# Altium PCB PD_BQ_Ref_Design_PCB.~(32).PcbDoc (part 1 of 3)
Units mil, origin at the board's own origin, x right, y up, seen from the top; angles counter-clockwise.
Board outline 2000 x 3702.76 mil, 4 copper layers (Top Layer, Signal Layer 1, Signal Layer 2, Bottom Layer), stack 61.2 mil thick; 124 components, 53 nets, 359 pads, 494 vias.
Unrouted connection lines stored in the file: 227.
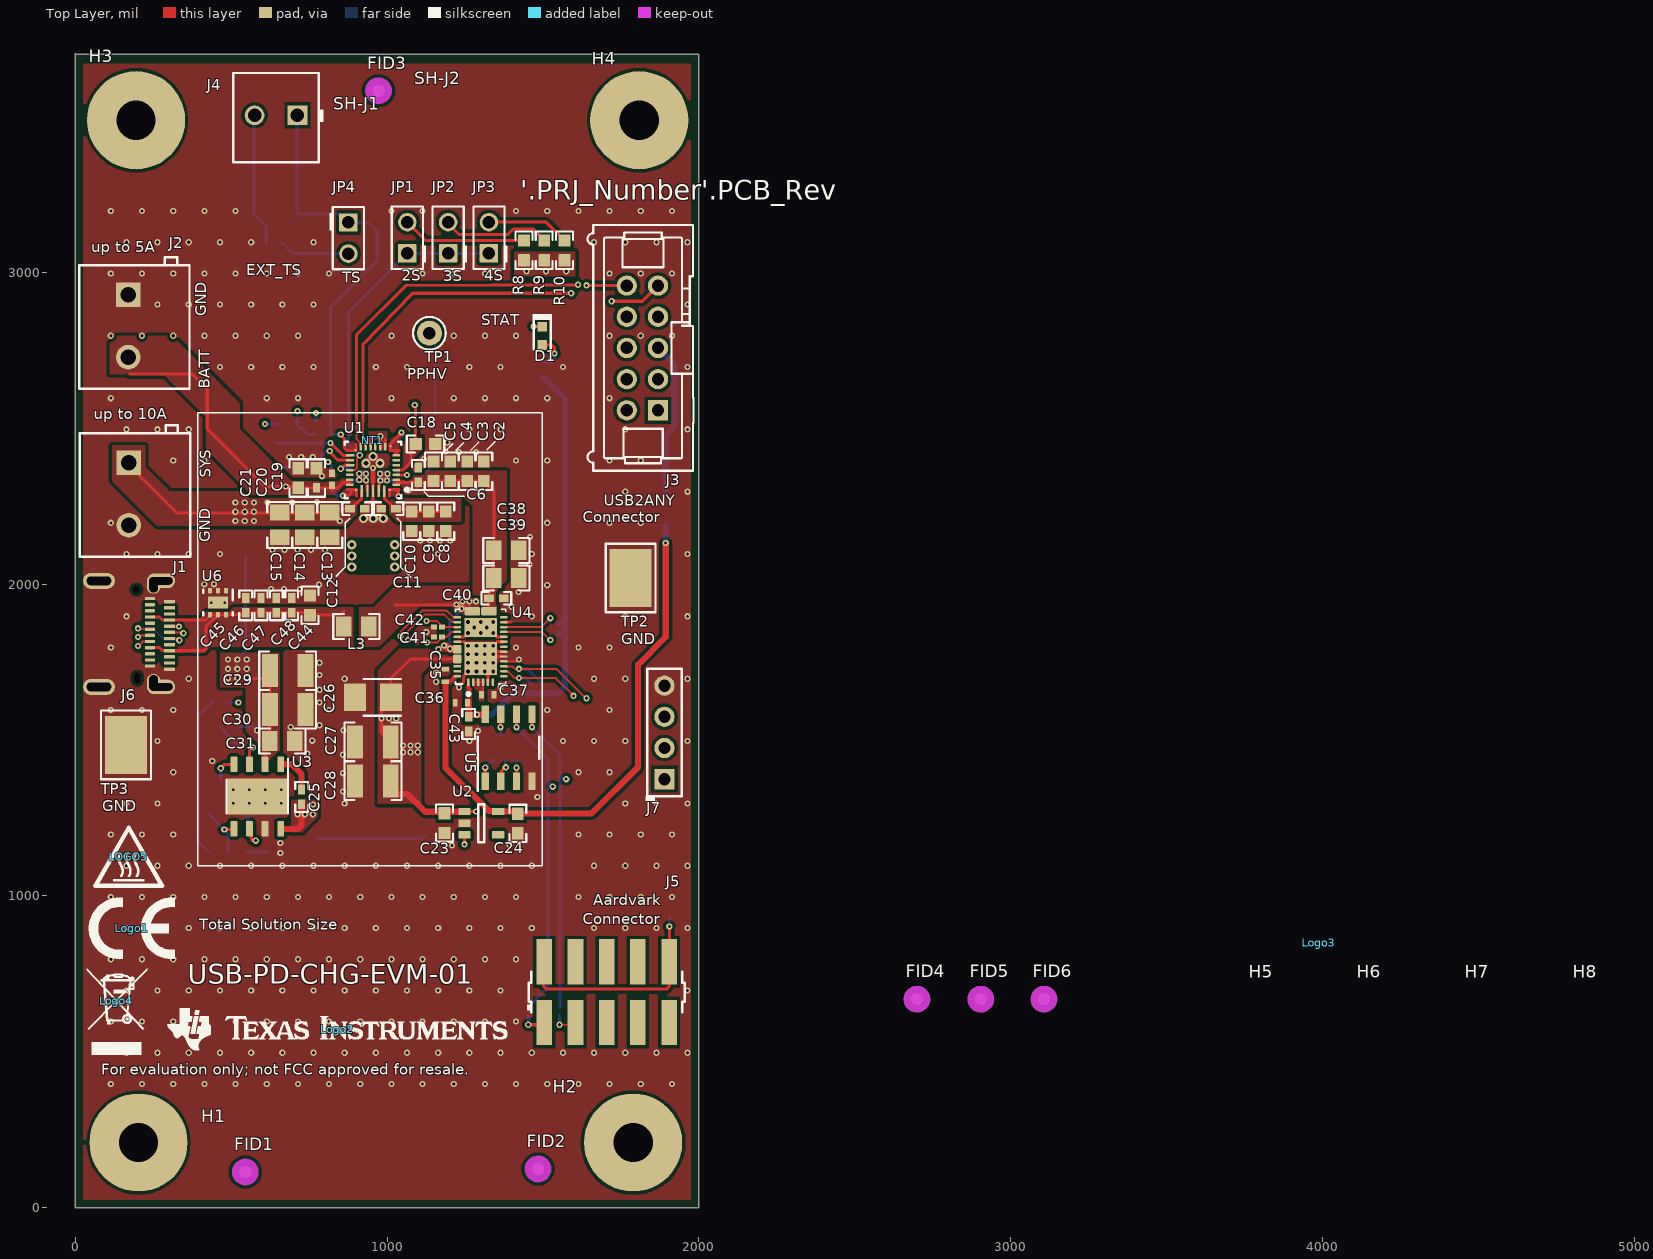
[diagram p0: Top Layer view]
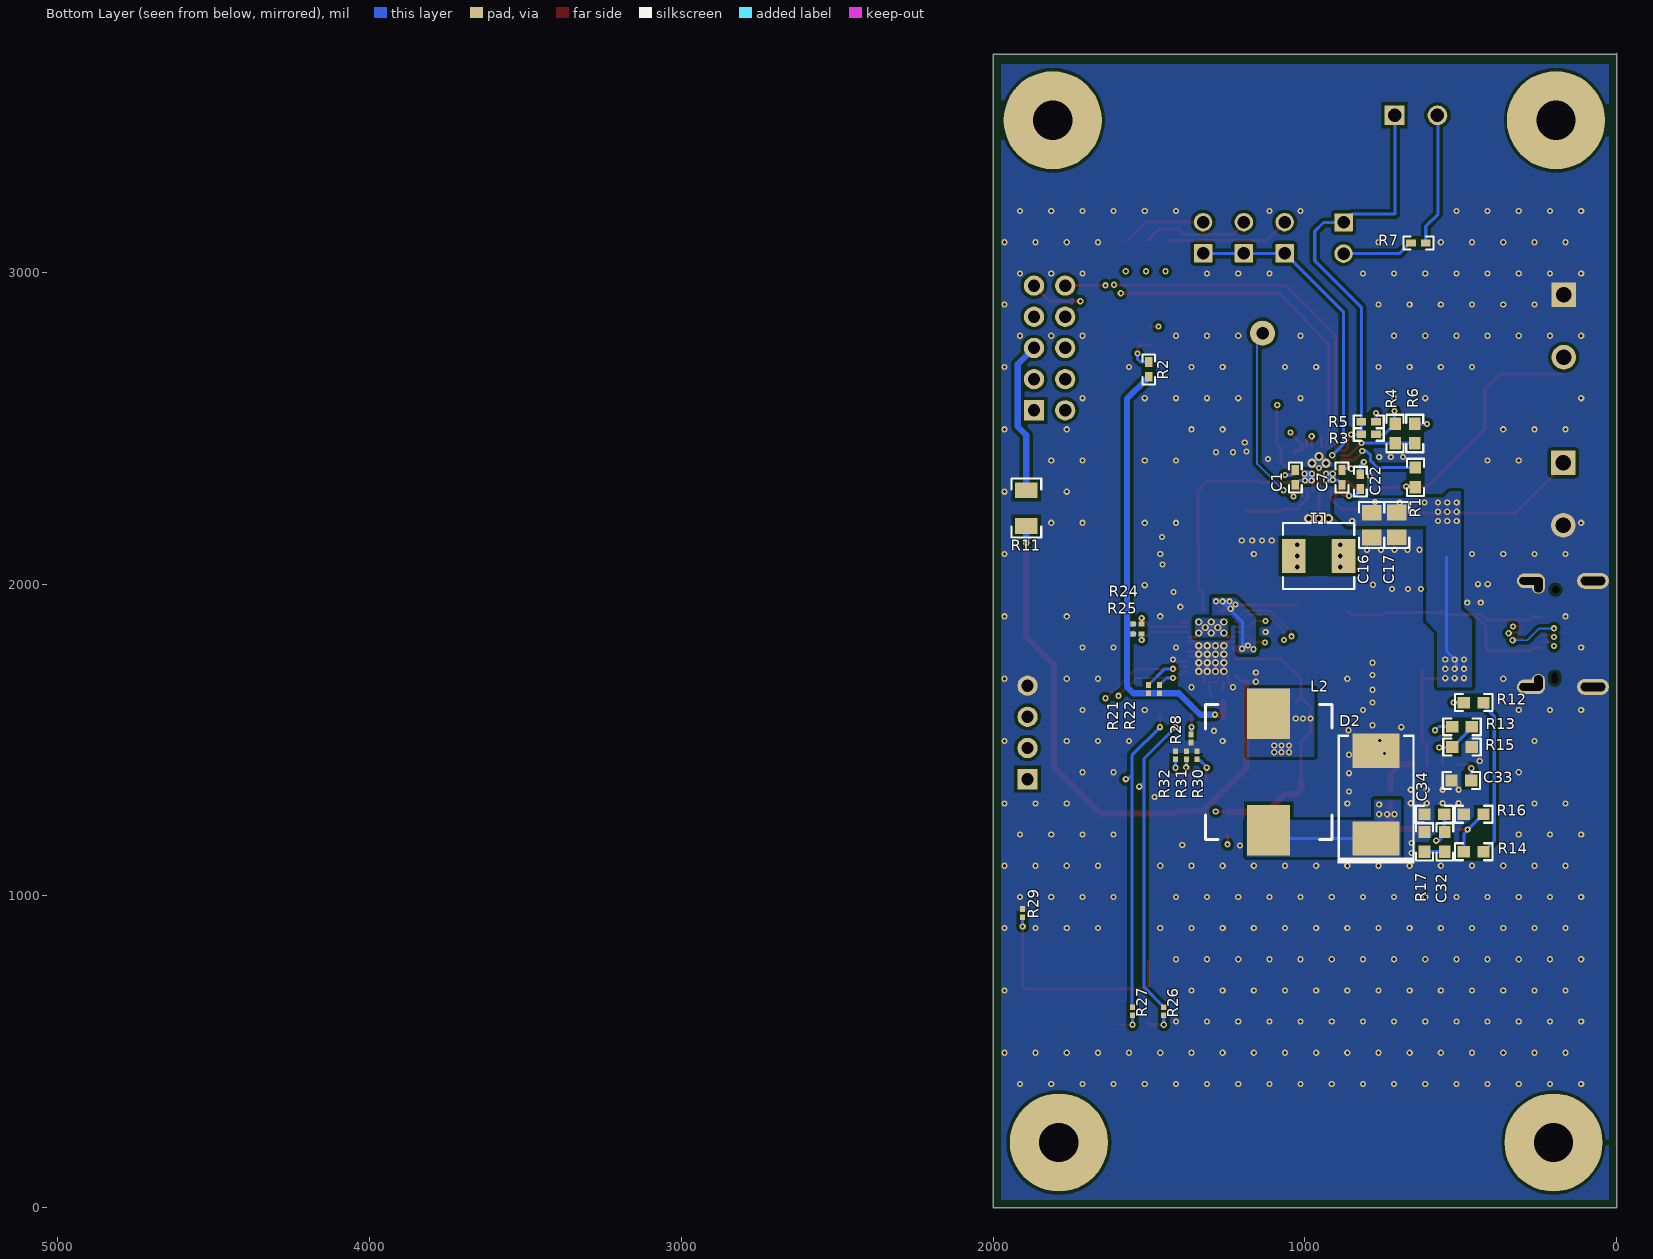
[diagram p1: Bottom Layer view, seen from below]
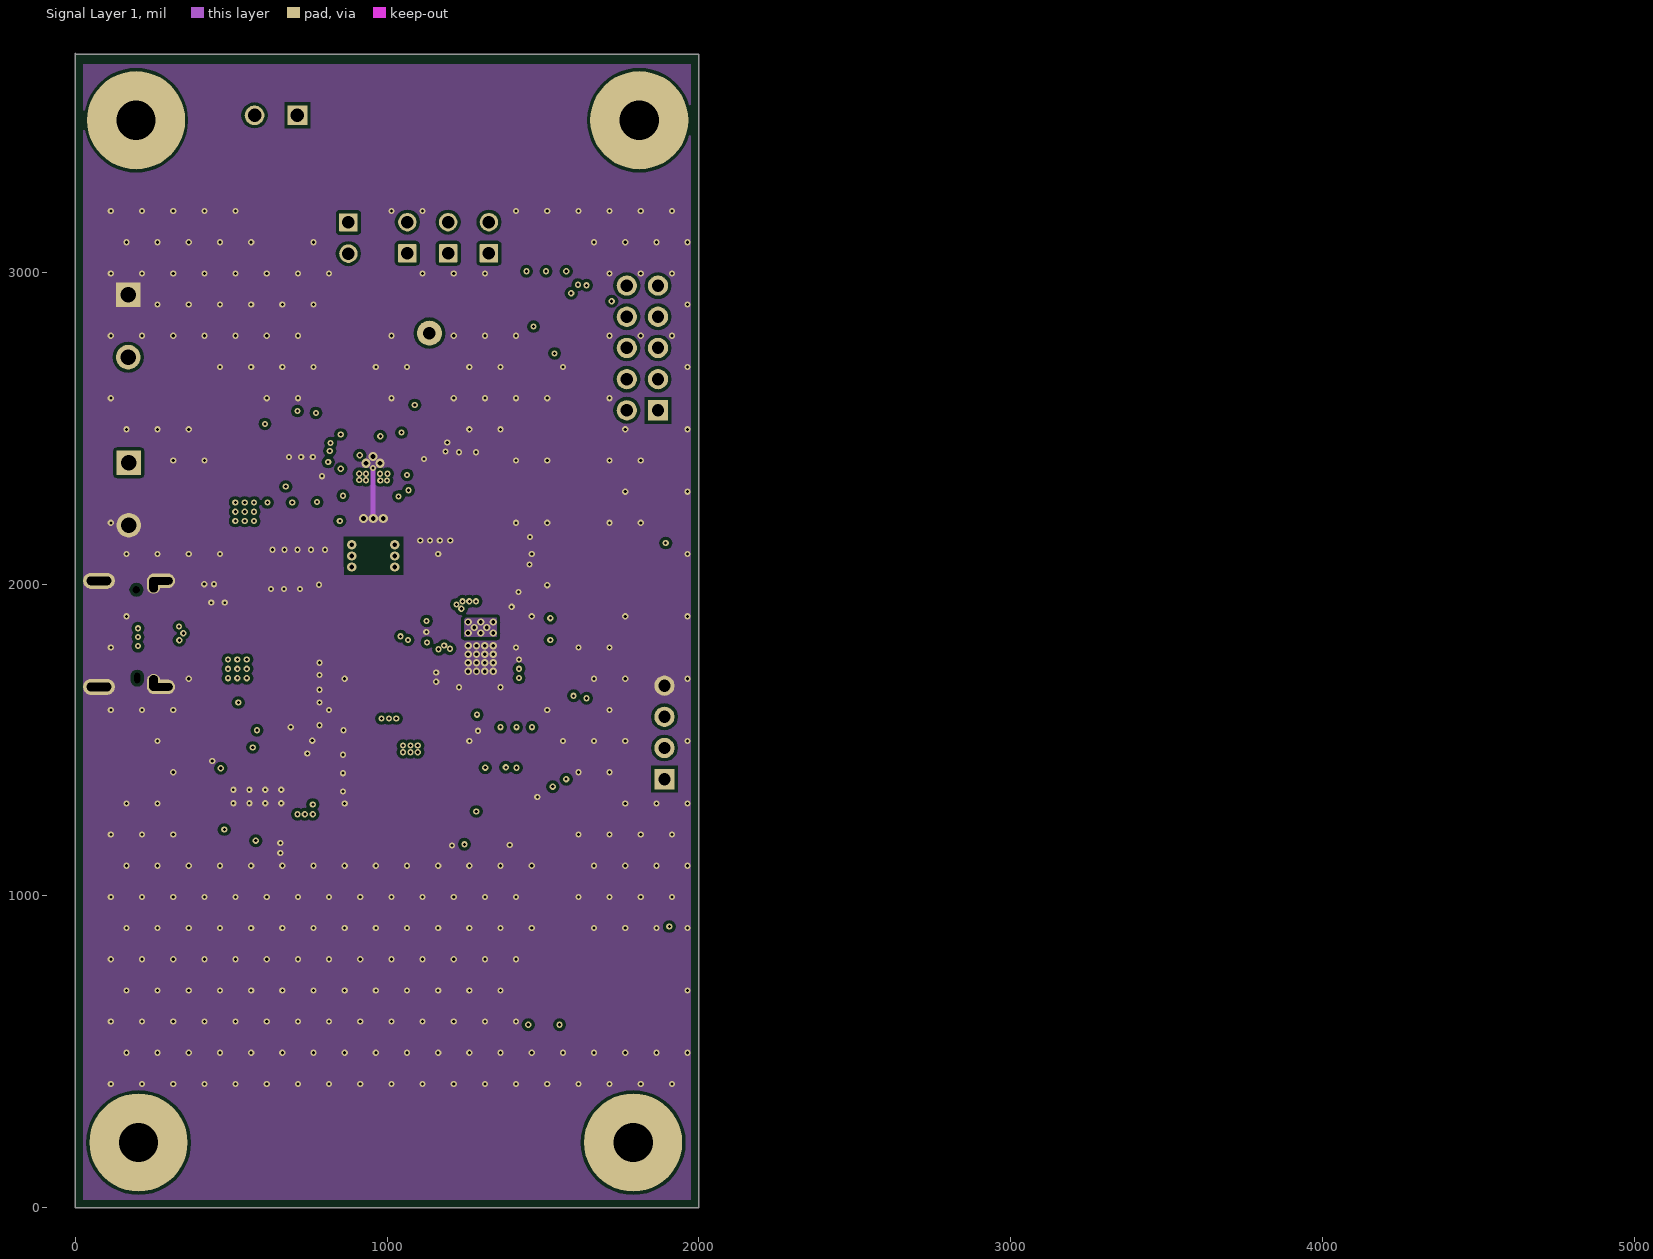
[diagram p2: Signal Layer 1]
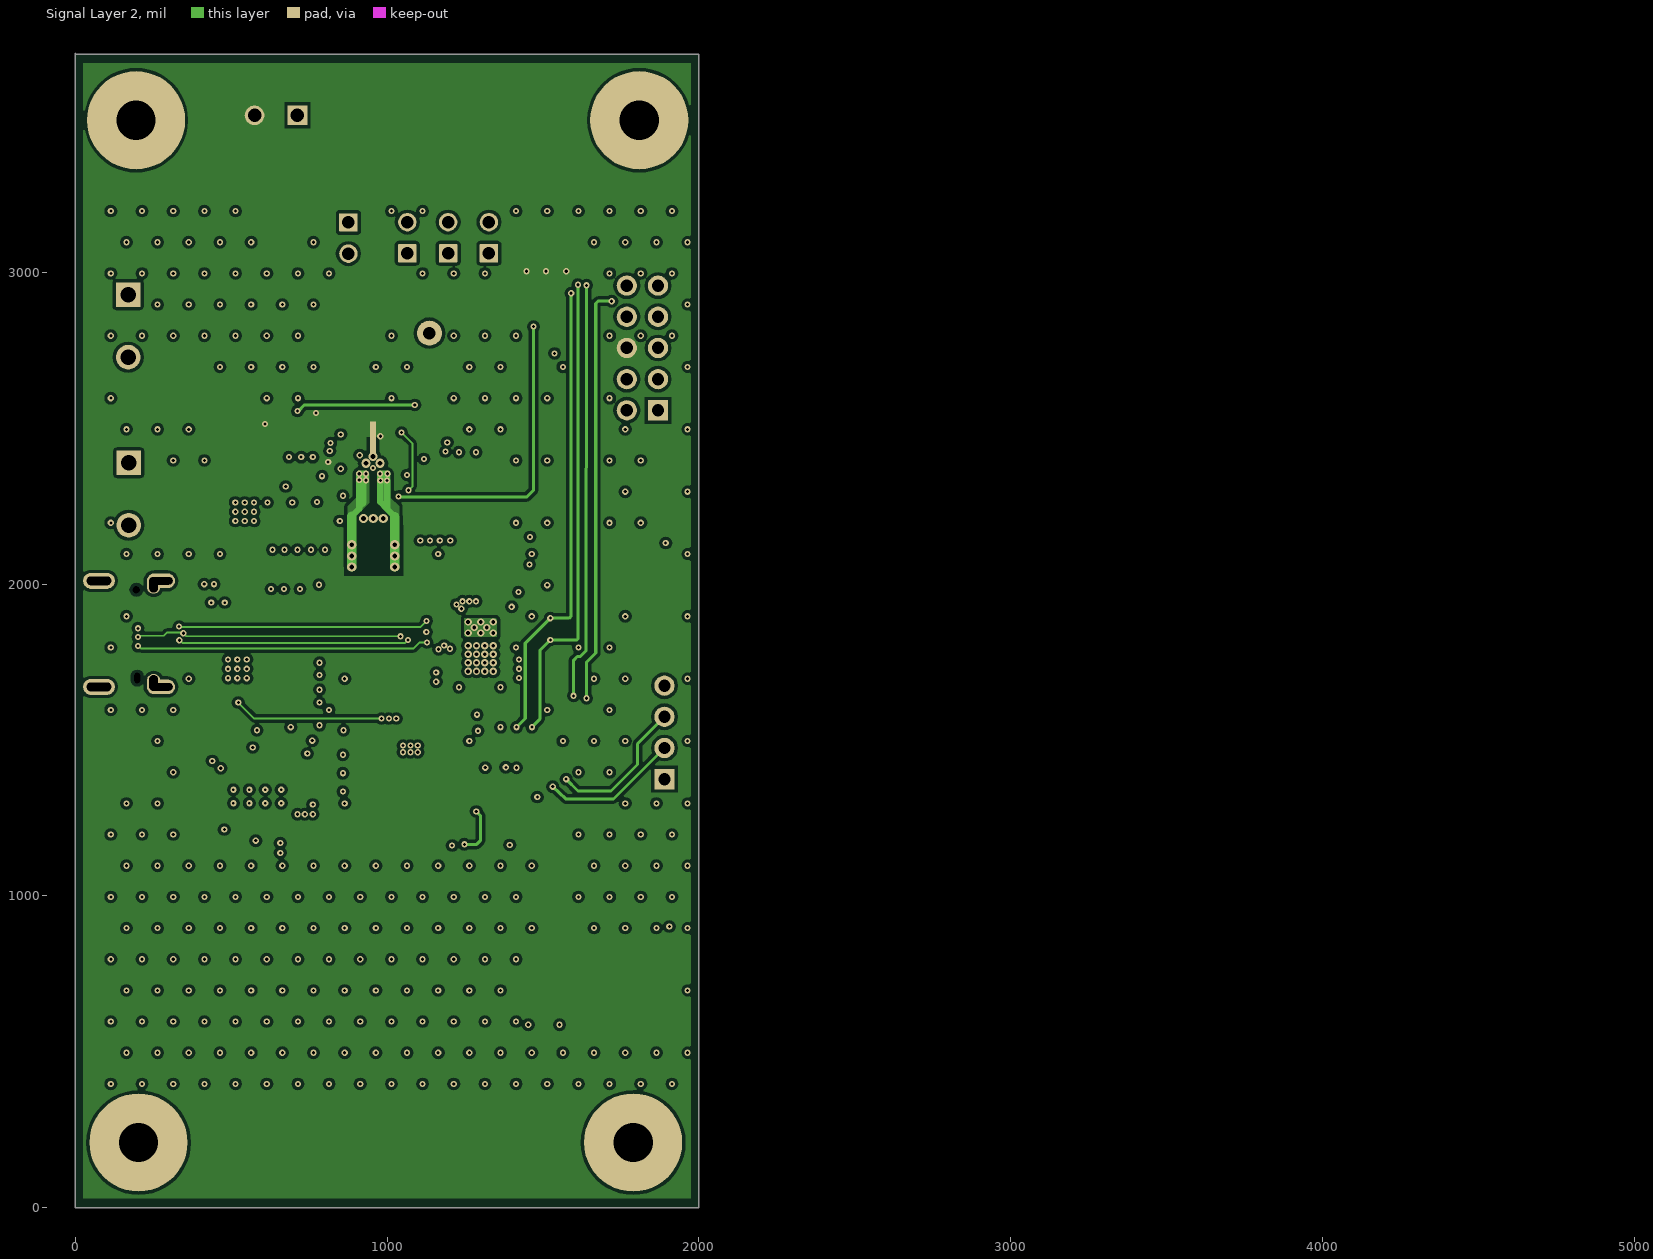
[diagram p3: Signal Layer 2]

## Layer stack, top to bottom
Top Solder: solder mask 0.4, Solder Resist, Dk 3.5
Top Layer: signal copper 2.8
Dielectric 1: prepreg 12, FR-4 High TG, Dk 4.2
Signal Layer 1: signal copper 2.8
Dielectric2: core 26, FR-4 High TG, Dk 4.2
Signal Layer 2: signal copper 2.8
Dielectric3: prepreg 12, FR-4 High TG, Dk 4.2
Bottom Layer: signal copper 2.8
Bottom Solder: solder mask 0.4, Solder Resist, Dk 3.5

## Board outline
0,0 2000,0 2000,3700 2.76,3700 0,3702.76

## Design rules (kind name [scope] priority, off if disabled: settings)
AcuteAngle [All] p1: minimum=4.50000000000000E+0001 checktracksonly=FALSE
AssemblyTestPointUsage [All] p1: valid=2
BoardOutlineClearance BoardOutlineClearance_MountingHoles [OnCopper and InComponentClass('Mounting Holes')] p1: gap=39.37 ignorepadtopadclearanceinfootprint=FALSE
BoardOutlineClearance BoardOutlineClearance_Poly [OnCopper and IsPoly] p2: gap=25 ignorepadtopadclearanceinfootprint=FALSE
BoardOutlineClearance [OnCopper and Not InComponentClass('Logo') and not InComponentClass('FiducialMark') and not InRegion(1000,500,4000,800) and not InPoly] p3: gap=15 ignorepadtopadclearanceinfootprint=FALSE
Clearance Clearance_Keepouts [((IsTrack Or IsArc) And Not InPoly) And IsFree and IsKeepOut vs ((IsTrack Or IsArc) And Not InPoly) And IsFree and IsKeepOut] p1: gap=0 ignorepadtopadclearanceinfootprint=FALSE
Clearance Clearance_Poly [InPolygon] p2: gap=10 ignorepadtopadclearanceinfootprint=TRUE
Clearance Clearance_FiducialMark [IsKeepOut and InComponentClass('FiducialMark') vs IsPad and InComponentClass('FiducialMark')] p3: gap=0 ignorepadtopadclearanceinfootprint=FALSE
Clearance [All] p4: gap=5 ignorepadtopadclearanceinfootprint=TRUE
ComponentClearance ComponentClearance_MountingHoles_FiducialMarks [InComponentClass('Mounting Holes') vs InComponentClass('FiducialMark')] p1: gap=50 collisioncheckmode=3 verticalgap=10 showdistances=FALSE
ComponentClearance ComponentClearance_Shunt [InComponentClass('Header') vs InComponentClass('Shunt')] p2: gap=0 collisioncheckmode=3 verticalgap=0 showdistances=FALSE
ComponentClearance ComponentClearance_Logo [InComponentClass('Logo')] p3: gap=50 collisioncheckmode=3 verticalgap=10 showdistances=FALSE
ComponentClearance ComponentClearance_ScrewToNut [(HasFootprint('NY PMS 440 0025 PH')) vs (HasFootprint('Keystone_1902C'))] p4: gap=5 collisioncheckmode=3 verticalgap=10 showdistances=FALSE
ComponentClearance ComponentClearance_MountingHoles [InComponentClass('Mounting Holes')] p5: gap=100 collisioncheckmode=3 verticalgap=100000 showdistances=FALSE
ComponentClearance ComponentClearance_SmallPassives [HasFootprint('0201*') or HasFootprint('0402*') or HasFootprint('0508') or HasFootprint('0603*') or HasFootprint('0612') or HasFootprint('0805*') or HasFootprint('0815*') or HasFootprint('0830*') or HasFootprint('1206*') or HasFootprint('1210*') or HasFootprint('1808*') or HasFootprint('1812*') or HasFootprint('1825*') or HasFootprint('2010*') or HasFootprint('2220*') or HasFootprint('2225*') or HasFootprint('2512*') or HasFootprint('2728*') or HasFootprint('3518*') vs HasFootprint('0201*') or HasFootprint('0402*') or HasFootprint('0508') or HasFootprint('0603*') or HasFootprint('0612') or HasFootprint('0805*') or HasFootprint('0815*') or HasFootprint('0830*') or HasFootprint('1206*') or HasFootprint('1210*') or HasFootprint('1808*') or HasFootprint('1812*') or HasFootprint('1825*') or HasFootprint('2010*') or HasFootprint('2220*') or HasFootprint('2225*') or HasFootprint('2512*') or HasFootprint('2728*') or HasFootprint('3518*')] p6: gap=14.96 collisioncheckmode=3 verticalgap=10 showdistances=FALSE
ComponentClearance ComponentClearance_THtoSMT [IsThruComponent vs IsSMTComponent] p7: gap=40 collisioncheckmode=3 verticalgap=30 showdistances=FALSE
ComponentClearance ComponentClearance_THtoTH [IsThruComponent vs IsThruComponent] p8: gap=30 collisioncheckmode=3 verticalgap=30 showdistances=FALSE
ComponentClearance [All] p9: gap=20 collisioncheckmode=3 verticalgap=10 showdistances=FALSE
DiffPairsRouting [All] p1: maxlimit=100 minlimit=10 mostfreqgap=10 toplayer_minwidth=15 toplayer_maxwidth=15 toplayer_prefwidth=15 midlayer1_minwidth=15 midlayer1_maxwidth=15 midlayer1_prefwidth=15 midlayer2_minwidth=15 midlayer2_maxwidth=15 midlayer2_prefwidth=15 bottomlayer_minwidth=15 bottomlayer_maxwidth=15 bottomlayer_prefwidth=15 maxuncoupledlength=1000
FabricationTestPointUsage TestPointUsage [All] p1: valid=2 allowmultiple=FALSE
FabricationTestpoint Testpoint [All] p1: side=3 testpointundercomponent=TRUE minsize=40 maxsize=100 preferedsize=60 minholesize=0 maxholesize=40 preferedholesize=32 testpointgrid=1 allowsidetop=TRUE allowsidebottom=TRUE usegrid=TRUE gridtolerance=0.01
FanoutControl Fanout_LCC [IsLCC] p1: bgadir=Out bgaviamode=Centered fanoutstyle=Auto fanoutdirection=Alternating viagrid=1 // Fanout_LCC (Default Rule)
FanoutControl Fanout_BGA [IsBGA] p2: bgadir=Out bgaviamode=Centered fanoutstyle=Auto fanoutdirection=Alternating viagrid=1 // Fanout_BGA (Default Rule)
FanoutControl Fanout_Default [All] p4: bgadir=Out bgaviamode=Centered fanoutstyle=Auto fanoutdirection=Alternating viagrid=1 // Fanout_Default (Default Rule)
FanoutControl Fanout_Small [(CompPinCount < 5)] p5: bgadir=Out bgaviamode=Centered fanoutstyle=Auto fanoutdirection=OutThenIn viagrid=1 // Fanout_Small (Default Rule)
HoleSize [All] p1: absolutevalues=TRUE maxlimit=251 minlimit=7.87 maxpercent=80.000 minpercent=20.000
MinimumAnnularRing MinimumAnnularRing_ThermalPadVias [IsVia and InAnyComponent] p1: minimumring=5.91
MinimumAnnularRing [All] p2: minimumring=5
MinimumSolderMaskSliver MinimumSolderMaskSliver_Logo [InComponentClass('Logo') vs InComponentClass('Logo')] p1: minsoldermaskwidth=0.7
MinimumSolderMaskSliver [All] p2: minsoldermaskwidth=3
PlaneConnect [All] p1: planeconnectstyle=Relief reliefexpansion=10 reliefentries=4 reliefconductorwidth=10 reliefairgap=10
PolygonConnect [All] p1: connectstyle=Direct reliefconductorwidth=10 reliefentries=4 polygonreliefangle="90 Angle" airgapwidth=10
RoutingVias ThermalPadVias [IsVia and InAnyComponent] p1: holewidth=7.87 width=19.68 viastyle="Through Hole" minholewidth=7.87 minwidth=19.68 maxholewidth=12.99 maxwidth=23.62
RoutingVias [All] p2: holewidth=10 width=20 viastyle="Through Hole" minholewidth=5 minwidth=10 maxholewidth=40 maxwidth=65
SilkToBoardRegionClearance [Not ((IsComment or IsDesignator) And (Hide <> 'False')) and not InRegion(1000,500,4000,800)] p1:
SilkToSilkClearance SilkToSilkClearance_Pb-FreeLogo [(HasFootprint('Pb-Free_Overlay_Medium') OR HasFootprint('Pb-Free_Overlay_Small')) vs (HasFootprint('Pb-Free_Overlay_Medium') OR HasFootprint('Pb-Free_Overlay_Small'))] p1: silktosilkclearance=0
SilkToSilkClearance [All] p2: silktosilkclearance=1
SilkToSolderMaskClearance SilkToComponentPadClearance [(IsPad or IsFill or IsRegion) and InAnycomponent] p1: minsilkscreentomaskgap=3 clearancetoexposedcopper=TRUE
SilkToSolderMaskClearance "Silk to Solder Mask Opening" [All] p2: minsilkscreentomaskgap=3.94 clearancetoexposedcopper=FALSE
SolderMaskExpansion [All] p1: expansion=1.97
UnRoutedNet [All] p1: checkbadconnections=TRUE
Width [All] p1: maxlimit=100 minlimit=6 preferedwidth=10 checkconnectedcopper=TRUE
14 further rules are at their usual default settings.

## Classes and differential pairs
component class Shunt: SH-J1 SH-J2
component class "Mounting Holes": H1 H2 H3 H4
component class FiducialMark: FID1 FID2 FID3 FID4 FID5 FID6
component class Logo: Logo2
component class Type_C_Port: C44 C45 C46 C47 C48 J6 L3 U6
component class TPS25750D: C35 C36 C37 C38 C39 C40 C41 C42 C43 J5 J7 R24 R25 R26 R27 R28 R29 R30 R31 R32 U4 U5
component class Power_5V_3.3V: C23 C24 C25 C26 C27 C28 C29 C30 C31 C32 C33 C34 D2 L2 R12 R13 R14 R15 R16 R17 U2 U3
component class Header: J5 J7 JP1 JP2 JP3 JP4
component class BQ25792: C1 C2 C3 C4 C5 C6 C7 C8 C9 C10 C11 C12 C13 C14 C15 C16 C17 C18 C19 C20 C21 C22 D1 J1 J2 J3 J4 JP1 JP2 JP3 JP4 L1 NT1 R1 R2 R3 R4 R5 R6 R7 R8 R9 R10 R11 R21 R22 TP1 TP2 TP3 U1
component class PD_BQ_Ref_Design_Hardware: FID1 FID2 FID3 FID4 FID5 FID6 H1 H2 H3 H4 H5 H6 H7 H8 Logo1 Logo2 Logo3 Logo4 LOGO5 SH-J1 SH-J2 ZZ1
component class AssemblyNote: ZZ1

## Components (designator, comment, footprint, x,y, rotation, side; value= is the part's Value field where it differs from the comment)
C1 "GRM155R71E473KA88D" 0402 1030.63,2342.52 r270 bottom value=0.047uF
C2 "GRT188R61E106ME13D" 0603#1 1310.16,2362.2 r270 top value=10uF
C3 "GRT188R61E106ME13D" 0603#1 1257.01,2362.2 r270 top value=10uF
C4 "GRT188R61E106ME13D" 0603#1 1202.87,2362.2 r270 top value=10uF
C5 "GRT188R61E106ME13D" 0603#1 1148.74,2362.2 r270 top value=10uF
C6 "C1005X7R1H104K050BE" 0402 1100.51,2350.39 r90 top value=0.1uF
C7 "GRM155R71E473KA88D" 0402 881.02,2342.52 r270 bottom value=0.047uF
C8 "GRT188R61E106ME13D" 0603#1 1188.11,2201.77 r90 top value=10uF
C9 "GRT188R61E106ME13D" 0603#1 1133.98,2201.77 r90 top value=10uF
C10 "GRT188R61E106ME13D" 0603#1 1078.86,2201.77 r90 top value=10uF
C11 "C1005X7R1H104K050BE" 0402 1005.04,2242.13 r180 top value=0.1uF
C12 "C1005X7R1H104K050BE" 0402 904.65,2242.13 r0 top value=0.1uF
C13 "C2012X5R1E106K125AB" 0805_HV 816.06,2189.96 r270 top value=10uF
C14 "C2012X5R1E106K125AB" 0805_HV 735.35,2189.96 r270 top value=10uF
C15 "C2012X5R1E106K125AB" 0805_HV 655.63,2189.96 r270 top value=10uF
C16 "C2012X5R1E106K125AB" 0805_HV 786.06,2189.61 r270 bottom value=10uF
C17 "C2012X5R1E106K125AB" 0805_HV 705.35,2189.96 r270 bottom value=10uF
C18 "GRM188R61C475KAAJ" 0603#1 1123.15,2449.8 r0 top value=4.7uF
C19 "C1005X7R1H104K050BE" 0402L 822.83,2336.61 r90 top value=0.1uF
C20 "GRT188R61E106ME13D" 0603#2 773.74,2340.55 r90 top value=10uF
C21 "GRT188R61E106ME13D" 0603#1 714.68,2340.55 r90 top value=10uF
C22 "C0402C102K5RACTU" 0402 821.97,2328.74 r90 bottom value=1000pF
C23 "GRT188R61E106ME13D" 0603#1 1184.05,1233.36 r90 top value=10uF
C24 "GRT188R61E106ME13D" 0603#1 1419.46,1232.38 r90 top value=10uF
C25 "C1005X7R1H104K050BE" 0402 725.65,1317.47 r270 top value=0.1uF
C26 "T520B107M006ATE015" 3528-21 954.72,1636.81 r180 top value=100uF
C27 "GRM32ER61A476KE20L" 1210_270 954.72,1494.09 r180 top value=47uF
C28 "GRM32ER61A476KE20L" 1210_270 954.72,1369.09 r180 top value=47uF
C29 "GRM32ER71H475KA88L" 1210_270 681.1,1722.44 r0 top value=4.7uF
C30 "GRM32ER71H475KA88L" 1210_270 681.1,1598.43 r0 top value=4.7uF
C31 "GRM216R71H103KA01D" 0805_HV 664.18,1496.75 r0 top value=0.01uF
C32 "GRM188R71H222KA01D" 0603#1 551.18,1173.23 r270 bottom value=2200pF
C33 "06031C103KAT2A" 0603#1 498.03,1370.08 r0 bottom value=0.01uF
C34 "GRM1885C1H220JA01D" 0603#1 584.65,1261.81 r0 bottom value=22pF
C35 "CL05A106MP5NUNC" 0402_070 1187.01,1706.69 r90 top value=10uF
C36 "CL05A106MP5NUNC" 0402_070 1238.19,1620.08 r180 top value=10uF
C37 "CL05A106MP5NUNC" 0402_070 1322.83,1645.67 r0 top value=10uF
C38 "C2012X5R1V226M125AC" 0805_HV 1382.69,2108.19 r0 top value=22uF
C39 "C2012X5R1V226M125AC" 0805_HV 1382.69,2019.61 r0 top value=22uF
C40 "GMK105BJ104KV-F" 0402 1350.39,1954.72 r0 top value=0.1uF
C41 "GRM033R71H331KA12D" 0201_033 1163.39,1830.71 r180 top value=330pF
C42 "GRM033R71H331KA12D" 0201_033 1163.39,1862.2 r180 top value=330pF
C43 "GMK105BJ104KV-F" 0402 1261.81,1551.18 r270 top value=0.1uF
C44 "GRM188R6YA475KE15D" 0603#1 752.95,1932.09 r90 top value=4.7uF
C45 "C0402C103J5RACTU" 0402 546.26,1932.09 r270 top value=0.01uF
C46 "C0402C103J5RACTU" 0402 595.47,1932.09 r270 top value=0.01uF
C47 "C0402C103J5RACTU" 0402 644.68,1932.09 r270 top value=0.01uF
C48 "C0402C103J5RACTU" 0402 693.9,1932.09 r270 top value=0.01uF
D1 "LTST-C190GKT" LED_LTST-C190 1498.03,2796.26 r90 top value=Green
D2 "CDBC540-G" SMC 771.65,1324.8 r90 bottom value=40V
FID1 "Fiducial" Fiducial10-20 545.28,114.17 r0 top
FID2 "Fiducial" Fiducial10-20 1484.25,124.02 r0 top
FID3 "Fiducial" Fiducial10-20 972.56,3582.68 r0 top
FID4 "Fiducial" Fiducial10-20 2699.73,668.75 r0 top
FID5 "Fiducial" Fiducial10-20 2904.45,668.75 r0 top
FID6 "Fiducial" Fiducial10-20 3107.2,668.75 r0 top
H1 "NY PMS 440 0025 PH" "NY PMS 440 0025 PH"#1 202.76,208.66 r0 top
H2 "NY PMS 440 0025 PH" "NY PMS 440 0025 PH"#2 1789.37,279.53 r0 top
H3 "NY PMS 440 0025 PH" "NY PMS 440 0025 PH"#1 194.88,3488.19 r0 top
H4 "NY PMS 440 0025 PH" "NY PMS 440 0025 PH"#1 1809.06,3488.19 r0 top
H5 "1902C" Keystone_1902C 3904.45,582.14 r0 top
H6 "1902C" Keystone_1902C 4250.9,582.14 r0 top
H7 "1902C" Keystone_1902C 4597.36,582.14 r0 top
H8 "1902C" Keystone_1902C 4943.82,582.14 r0 top
J1 "ED120/2DS" On-Shore_ED120_2DS 171.26,2289.37 r270 top
J2 "ED120/2DS" On-Shore_ED120_2DS 169.29,2828.35 r270 top
J3 "N2510-6002-RB" CONN_2510-6002 1819.09,2757.68 r90 top
J4 "0393570002" MOLEX_39357-0002 643.7,3503.94 r180 top
J5 "TSM-105-01-L-DV-P" Samtec_TSM-105-01-x-DV 1704.54,691.02 r90 top
J6 "DX07S024JJ2R1300" JAE_DX07S024JJ2R1300 4.92,1840.55 r270 top
J7 "PEC04SAAN" SULLINS_PEC04SAAN 1889.76,1524.41 r90 top
JP1 "Header_2x1" CONN_PEC02SAAN 1064.96,3111.22 r90 top
JP2 "Header_2x1" CONN_PEC02SAAN 1195.87,3111.22 r90 top
JP3 "Header_2x1" CONN_PEC02SAAN 1326.77,3111.22 r90 top
JP4 "Header_2x1" CONN_PEC02SAAN 875.98,3110.24 r270 top
L1 "IHLP2020BZER1R0M11" IHLP-2020BZ 955.83,2090.43 r180 bottom value=1uH
L2 "74437368047" WE-LHMI_1040 1116.14,1397.64 r90 bottom value=4.7uH
L3 "FBMJ2125HM210NT" 0805_HV 901.57,1864.17 r0 top value="21 ohm"
Logo1 "CE Mark" CE_Mark_5mm 181.1,895.67 r0 top
Logo2 "Texas Instruments" TI_Horizontal_Overlay_Small 840.55,572.83 r0 top
Logo3 "FCC disclaimer" FCC_disclaimer 3989.17,850.39 r0 top
Logo4 "WEEE logo" WEEE_Minimum 131.89,663.39 r0 top
LOGO5 "CAUTION HOT SURFACE" IEC_HotSurface_Small 171.26,1125.98 r0 top
NT1 "Net-Tie" Net-Tie_20milWide_60milLong 954.72,2461.1 r90 top net-tie
R1 "RC0603FR-07100RL" 0603#1 645.67,2342.52 r90 bottom value=100
R2 "CRCW04022K21FKED" 0402 1500.98,2688.98 r270 bottom value=2.21k
R3 "Resistor" 0402 795.39,2480.31 r180 bottom value=5.23k
R4 "RC0603FR-07137KL" 0603#1 710.68,2483.27 r90 bottom value=137k
R5 "Resistor" 0402 795.39,2520.67 r0 bottom value=30.1k
R6 "RC0603FR-07100KL" 0603#1 647.82,2483.27 r270 bottom value=100k
R7 "Resistor" 0402 635.83,3094.49 r0 bottom value=10.0k
R8 "RC0603FR-076K04L" 0603#1 1438.98,3070.87 r90 top value=6.04k
R9 "CRCW060310K5FKEA" 0603#1 1503.94,3070.87 r90 top value=10.5k
R10 "CRCW060317K4FKEA" 0603#1 1568.9,3070.87 r90 top value=17.4k
R11 "ERJ-8ENF10R0V" 1206 1893.7,2244.09 r270 bottom value=10.0
R12 "CRCW060351R1FKEA" 0603#1 458.66,1620.08 r0 bottom value=51.1
R13 "CRCW0603665KFKEA" 0603#1 496.06,1542.32 r0 bottom value=665k
R14 "CRCW060310K2FKEA" 0603#1 458.66,1141.73 r180 bottom value=10.2k
R15 "CRCW0603130KFKEA" 0603#1 496.06,1477.36 r0 bottom value=130k
R16 "CRCW06031K96FKEA" 0603#1 458.66,1261.81 r180 bottom value=1.96k
R17 "CRCW060337K4FKEA" 0603#1 616.14,1173.23 r270 bottom value=37.4k
R21 "CRCW02012K20FKED" 0201 1501.97,1663.39 r270 bottom value=2.20k
R22 "CRCW02012K20FKED" 0201 1466.54,1663.39 r270 bottom value=2.20k
R24 "CRCW02012K20FKED" 0201 1537.4,1872.05 r180 bottom value=2.20k
R25 "CRCW02012K20FKED" 0201 1537.4,1840.55 r180 bottom value=2.20k
R26 "CRCW02010000Z0ED" 0201 1452.76,629.92 r270 bottom value=0
R27 "CRCW02010000Z0ED" 0201 1553.15,629.92 r270 bottom value=0
R28 "CRCW020110K0FKED" 0201 1365.16,1504.92 r90 bottom value=10.0k
R29 "CRCW02010000Z0ED" 0201 1905.51,944.88 r270 bottom value=0
R30 "CRCW020110K0FKED" 0201 1346.46,1450.79 r270 bottom value=10.0k
R31 "CRCW020110K0FKED" 0201 1379.92,1450.79 r270 bottom value=10.0k
R32 "CRCW020110K0FKED" 0201 1415.35,1450.79 r270 bottom value=10.0k
SH-J1 "SNT-100-BK-G" SNT-100-BK-G 870.08,3395.67 r90 top value=1x2
SH-J2 "SNT-100-BK-G" SNT-100-BK-G 1129.92,3476.38 r90 top value=1x2
TP1 "5000" Keystone5000 1135.83,2805.12 r90 top
TP2 "5016" Testpoint_Keystone_Compact 1781.5,2019.69 r90 top
TP3 "5016" Testpoint_Keystone_Compact 162.4,1484.25 r270 top
U1 "BQ25792RQM" RQM0029A-MFG 954.84,2366.04 r180 top
U2 "TLV75533PDBVR" DBV0005A_N 1302.17,1233.36 r0 top
U3 "TPS54531DDAR" DDA0008E_L 583.66,1318.62 r270 top
U4 "TPS25750DRJK" RJK0038B-C01-MFG 1300.01,1799.39 r90 top
U5 "CAT24C256WI-G" SOIC-8 1389.96,1475.32 r90 top
U6 "TVS2200DRVR" DRV0006A 457.68,1940.94 r270 top
ZZ1 "This Assembly Note is for PCB labels only" AssemblyNoteLabel 190.91,4268.71 r0 top

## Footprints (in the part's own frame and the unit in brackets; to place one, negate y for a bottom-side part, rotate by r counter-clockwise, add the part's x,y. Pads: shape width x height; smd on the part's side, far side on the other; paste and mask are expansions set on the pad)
0201 [mm] "Data from Kemet datasheet CC101_COM dated 7/28/11"
  rect 0.46x0.42 smd: 1(-0.33,0) 2(0.33,0)
  body extent -0.31,-0.16 0.31,0.16, height 0.26
0201_033 [mm] "SMD, 2-Leads, Height 0.33mm"
  rect 0.46x0.42 smd: 1(-0.33,0) 2(0.33,0)
  body extent -0.31,-0.16 0.31,0.16, height 0.33
0402 [mm] "0402 from SM-752 data"
  rect 0.8x0.6 smd: 1(-0.6,0) 2(0.6,0)
  silkscreen extent -1.22,-0.52 1.22,0.52, body extent -0.55,-0.3 0.55,0.3, height 0.6
0402_070 [mil] "SMD, 2-Leads, Body 1.2x0.7mm, Height 0.7mm"
  rect 15x24 smd: 1(-20,0) 2(20,0)
  body extent -24,-14 24,14, height 28
0402L [mm] "0402 from SM-752 data"
  rect 0.6x0.5 smd: 1(-0.5,0) 2(0.5,0)
  body extent -0.55,-0.3 0.55,0.3, height 0.6
0603#1 [mm] "0603 from SM-752 data"
  rect 1x0.95 smd: 1(-0.8,0) 2(0.8,0)
  silkscreen extent -1.52,-0.69 1.52,0.69, body extent -0.87,-0.47 0.87,0.47, height 1
0603#2 [mm] "0603 from SM-752 data"
  rect 0.8x0.6 smd: 1(-0.8,0)
  rect 1x0.95 smd: 2(0.8,0)
  silkscreen extent -1.52,-0.69 1.52,0.69, body extent -0.87,-0.47 0.87,0.47, height 1
0805_HV [mil] "0805 with 30mil clearance between pads"
  rect 50x63 smd: 1(-40,0) 2(40,0)
  silkscreen extent -74,-40 74,40, body extent -43,-29 43,29, height 57
1206 [mm] "1206 from SM-752 data"
  rect 1.3x1.85 smd: 1(-1.45,0) 2(1.45,0)
  silkscreen extent -2.4,-1.21 2.4,1.21, body extent -1.7,-0.9 1.7,0.9, height 1.35
1210_270 [mm] "1210"
  rect 1.3x2.7 smd: 1(-1.45,0) 2(1.45,0)
  silkscreen extent -2.32,-1.57 2.32,1.57, body extent -1.7,-1.35 1.7,1.35, height 2.7
3528-21 [mm] "Medium Density IPC, based on Kemet datasheet 2016-10-20"
  rrect6% 1.8x2.23 smd: 1(-1.46,0) 2(1.46,0)
  silkscreen extent -2.29,-1.5 0.76,1.5, body extent -1.85,-1.5 1.85,1.5, height 2.12
AssemblyNoteLabel [mil] "Assembly Note for PCB Labels"
CE_Mark_5mm [mil] "Minimum text height for CE Mark"
  silkscreen extent -138,-98 138,98
CONN_2510-6002 [mm] "3M 2500 series TS-0770-L December 15, 2011"
  rect 1.65x1.65 hole 1.016: 1(-5.08,-1.27)
  round 1.65 hole 1.016: 2(-5.08,1.27) 3(-2.54,-1.27) 4(-2.54,1.27) 5(0,-1.27) 6(0,1.27) 7(2.54,-1.27) 8(2.54,1.27) 9(5.08,-1.27) 10(5.08,1.27)
  silkscreen extent -10.01,-4.17 10.01,4.47, body extent -10.01,-4.11 10.01,4.52, height 9.92
CONN_PEC02SAAN [mm] "SULLINS"
  rrect7% 1.5x1.5 hole 1.016: 1(-1.27,0)
  round 1.5 hole 1.016: 2(1.27,0)
  silkscreen extent -2.54,-1.52 2.54,1.27, body extent -2.54,-1.27 2.54,1.27, height 8.38
DBV0005A_N [mm] "SOT23, 5-Leads, Body 2.9x1.6mm, Pitch 0.95mm, Lead Span 2.8mm, IPC Medium Density"
  rrect17% 1x0.6 smd: 1(-1.375,0.95) 2(-1.375,0) 3(-1.375,-0.95) 4(1.375,-0.95) 5(1.375,0.95)
  silkscreen extent -0.25,-1.55 0.25,1.55, body extent -1.42,-1.46 1.42,1.46, height 1.09
DDA0008E_L [mm]
  rrect18% 1.25x0.55 smd: 1(-2.625,1.905) 2(-2.625,0.635) 3(-2.625,-0.635) 4(-2.625,-1.905) 5(2.625,-1.905) 6(2.625,-0.635) 7(2.625,0.635) 8(2.625,1.905)
  rrect7% 2.95x4.9 smd: 9(0,0)
  rrect4% 2.4x3.1 on Top Paste: 9(0,0)
  rrect4% 2.4x3.1 on Top Solder: 9(0,0)
  silkscreen extent -3.13,-2.5 1.4,2.5, body extent -3,-2.45 3,2.45, height 1.57
DRV0006A [mm] "SON, 6-Leads, Body 2x2mm, Pitch 0.65mm, Thermal Pad 1.6x1mm, TI Recommended"
  rrect33% 0.45x0.3 smd: 1(-0.975,0.65) 2(-0.975,0) 3(-0.975,-0.65) 4(0.975,-0.65) 5(0.975,0) 6(0.975,0.65)
  rrect14% 1x0.7 on Top Paste: 7(0,0.45) 7(0,-0.45)
  rrect10% 1x1.6 smd paste-0.5: 7(0,0)
  silkscreen extent -1.05,-1.2 1.05,1.2, body extent -1.05,-1.05 1.05,1.05, height 0.81
FCC_disclaimer [mil]
Fiducial10-20 [mm]
  round 1 smd mask+0.5: 1(0,0)
  Top Layer keep-out circle w1.178: c0,0 r0.5
IEC_HotSurface_Small [mil]
  silkscreen extent -107,-93 107,92
IHLP-2020BZ [mm] "Vishay Dale recommended land pattern.  Document 34261 rev 12-Sept-13"
  rect 1.915x2.79 smd: 1(-2.037,0) 2(2.037,0)
  silkscreen extent -2.9,-2.7 2.9,2.7, body extent -2.87,-2.72 2.87,2.72, height 2
JAE_DX07S024JJ2R1300 [mm] "Receptacle, USB 3.1 Type C, R/A, SMT"
  rrect37% 0.27x0.9 smd: A1(-2.625,7.55) A2(-2.125,7.55) A3(-1.625,7.55) A4(-1.125,7.55) A5(-0.625,7.55) A6(-0.125,7.55) A7(0.375,7.55) A8(0.875,7.55) A9(1.375,7.55) A10(1.875,7.55) A11(2.375,7.55) A12(2.875,7.55)
  round 0.3 hole 0.6 unplated: ALIGN1(-3.6,4.85)
  rrect100% 0.55x0.3 hole 0.5 slot 0.85 at 0 deg unplated: ALIGN2(3.6,4.915)
  rrect37% 0.27x0.8 smd: B1(2.625,5.95) B2(2.125,5.95) B3(1.625,5.95) B4(1.125,5.95) B5(0.625,5.95) B6(0.125,5.95) B7(-0.375,5.95) B8(-0.875,5.95) B9(-1.375,5.95) B10(-1.875,5.95) B11(-2.375,5.95) B12(-2.875,5.95)
  rrect100% 1.2x2.3 hole 0.6 slot 1.9 at 90 deg: S1(-4.32,6.85) S2(4.32,6.85)
  rrect100% 1.45x1.1 hole 0.7 slot 1.25 at 0 deg: S1(-3.995,6.25) S2(3.995,6.25)
  rrect100% 1.3x2.6 hole 0.7 slot 2 at 90 deg: S3(-4.32,1.8) S4(4.32,1.8)
  body extent -4.47,-0.5 4.47,7.67, height 3.14
Keystone5000 [mil] "For Keystone 500x miniature loop terminals"
  round 80 hole 40: 1(0,0)
  silkscreen extent -52,-52 52,52, body extent -49,-49 49,49, height 182
Keystone_1902C [mil] "Hex Standoff, 4-40 threaded, nylon"
  round 1 on Mech3: 0(0,0)
  body extent -145,-126 146,126, height 501
LED_LTST-C190 [mm] "Lite-On"
  rect 0.8x0.8 smd: 1(-0.75,0) 2(0.75,0)
  silkscreen extent -1.1,-0.8 1.8,0.8, body extent -0.85,-0.45 0.85,0.45, height 0.9
MOLEX_39357-0002 [mm] "Terminal Block, 3.5 mm, 2x1, TH"
  rect 1.6x1.6 hole 1.1: 1(-1.75,0)
  round 1.6 hole 1.1: 2(1.75,0)
  silkscreen extent -3.86,-3.45 3.5,3.84, body extent -3.55,-3.45 3.56,3.84, height 8.51
Net-Tie_20milWide_60milLong [mil] "20mil net tie, no solder mask opening, no solder paste"
  rect 60x20 on Mid2: 1(-30,0) 2(30,0)
"NY PMS 440 0025 PH"#1 [mm] "4-40 nylon screw and mounting hole"
  round 8 hole 3.2: 1(0,0)
  body extent -3.3,-3.3 3.3,3.3, height 2.69
"NY PMS 440 0025 PH"#2 [mm] "4-40 nylon screw and mounting hole"
  round 8 hole 3.2: 1(0,-1.8)
  body extent -3.3,-3.3 3.3,3.3, height 2.69
On-Shore_ED120_2DS [mm] "ONSHORE"
  rrect5% 2x2 hole 1.25: 1(-2.54,0)
  round 2 hole 1.25: 2(2.54,0)
  silkscreen extent -5.6,-4 5.12,5, body extent -5.78,-4 5.08,5, height 13
RJK0038B-C01-MFG [mm]
  rrect50% 0.6x0.2 smd paste+0 mask-1000: 1(-2.9,1) 2(-2.9,0.6) 3(-2.9,0.2) 4(-2.9,-0.2) 5(-2.9,-0.6) 6(-2.9,-1)
  rrect50% 0.2x0.6 smd paste+0 mask-1000: 7(-2.4,-1.9) 8(-2,-1.9) 9(-1.6,-1.9) 10(-1.2,-1.9) 11(-0.8,-1.9) 12(-0.4,-1.9) 13(0,-1.9) 14(0.4,-1.9) 15(0.8,-1.9) 16(1.2,-1.9) 17(1.6,-1.9) 18(2,-1.9) 19(2.4,-1.9) 26(2.4,1.9) 27(2,1.9) 28(1.6,1.9) 29(1.2,1.9) 30(0.8,1.9) 31(0.4,1.9) 36(-1.6,1.9) 37(-2,1.9) 38(-2.4,1.9)
  rrect50% 0.4x0.2 smd paste-1000 mask-1000: 20(2.8,-1.1) 21(2.8,-0.65) 22(2.8,-0.2) 23(2.8,0.2) 24(2.8,0.65) 25(2.8,1.1)
  rrect50% 0.2x0.4 smd paste-1000 mask-1000: 32(0,1.8) 33(-0.4,1.8) 34(-0.8,1.8) 35(-1.2,1.8)
  rrect4% 2.72x2.65 smd paste-1000 mask-1000: 39(-0.965,0)
  rrect7% 1.53x2.65 smd paste-1000 mask-1000: 40(1.56,0)
  rrect29% 0.7x0.7 smd paste-1000 mask-1000: ""(-1,1.9) ""(-0.2,1.9)
  rrect29% 0.7x1.253 smd paste-1000 mask-1000: ""(2.9,-0.677) ""(2.9,0.677)
  silkscreen extent -3.97,-2.05 3.05,2.05, body extent -3.3,-2.3 3.35,2.35, height 0.25
RQM0029A-MFG [mm]
  round 0.192 smd: 1(-1.369,1.631)
  rrect50% 0.6x0.2 smd: 2(-1.9,1.2) 3(-1.9,0.8) 4(-1.9,0.4) 5(-1.9,0) 6(-1.9,-0.4) 7(-1.9,-0.8) 8(-1.9,-1.2) 20(1.9,0) 21(1.9,0.4) 22(1.9,0.8) 23(1.9,1.2)
  round 0.158 smd: 9(-1.412,-1.937)
  rrect50% 0.2x0.6 smd: 10(-1,-1.9) 11(-0.6,-1.9) 12(-0.2,-1.9) 13(0.2,-1.9) 14(0.6,-1.9) 15(1,-1.9)
  round 0.175 smd: 16(1.431,-1.631) 24(1.381,1.631)
  rrect50% 0.7x0.2 smd: 17(1.85,-1.2)
  rrect50% 0.65x0.2 smd: 18(1.875,-0.8)
  rrect50% 0.68x0.2 smd: 19(1.86,-0.4)
  rrect50% 0.2x1 smd: 25(0.9,1.7) 26(0.45,1.7) 27(0,1.7) 28(-0.45,1.7)
  rrect50% 0.2x0.95 smd: 29(-0.9,1.725)
  Top Layer region: 2.2,1.65 2.196,1.669 2.185,1.685 2.169,1.696 2.15,1.7 2.15,1.7 1.45,1.7 1.45,2.15 1.446,2.169 1.435,2.185 1.419,2.196 1.4,2.2 1.4,2.2 1.3,2.2 1.275,2.193 1.257,2.175 1.25,2.15 1.25,2.15 1.25,1.55 1.254,1.531 1.265,1.515 1.281,1.504 1.3,1.5 1.3,1.5 2.15,1.5 2.169,1.504 2.185,1.515 2.196,1.531 2.2,1.55 2.2,1.55
  Top Layer region: 2.2,-1.65 2.193,-1.675 2.175,-1.693 2.15,-1.7 2.15,-1.7 1.5,-1.7 1.5,-2.15 1.496,-2.169 1.485,-2.185 1.469,-2.196 1.45,-2.2 1.45,-2.2 1.35,-2.2 1.325,-2.193 1.307,-2.175 1.3,-2.15 1.3,-2.15 1.3,-1.55 1.304,-1.531 1.315,-1.515 1.331,-1.504 1.35,-1.5 1.35,-1.5 2.15,-1.5 2.169,-1.504 2.185,-1.515 2.196,-1.531 2.2,-1.55 2.2,-1.55
  Top Layer region: -2.2,-1.65 -2.193,-1.675 -2.175,-1.693 -2.15,-1.7 -2.15,-1.7 -1.5,-1.7 -1.5,-2.15 -1.496,-2.169 -1.485,-2.185 -1.469,-2.196 -1.45,-2.2 -1.45,-2.2 -1.35,-2.2 -1.331,-2.196 -1.315,-2.185 -1.304,-2.169 -1.3,-2.15 -1.3,-2.15 -1.3,-1.55 -1.304,-1.531 -1.315,-1.515 -1.331,-1.504 -1.35,-1.5 -1.35,-1.5 -2.15,-1.5 -2.169,-1.504 -2.185,-1.515 -2.196,-1.531 -2.2,-1.55 -2.2,-1.55
  Top Layer region: -2.2,1.65 -2.193,1.675 -2.175,1.693 -2.15,1.7 -2.15,1.7 -1.45,1.7 -1.45,2.15 -1.443,2.175 -1.425,2.193 -1.4,2.2 -1.4,2.2 -1.3,2.2 -1.275,2.193 -1.257,2.175 -1.25,2.15 -1.25,2.15 -1.25,1.55 -1.254,1.531 -1.265,1.515 -1.281,1.504 -1.3,1.5 -1.3,1.5 -2.15,1.5 -2.169,1.504 -2.185,1.515 -2.196,1.531 -2.2,1.55 -2.2,1.55
  silkscreen extent -2.88,-2.3 2.3,2.3, body extent -2.3,-2.3 2.3,2.3, height 0.25
Samtec_TSM-105-01-x-DV [mm] "Header, 2.54mm, 5x2, SMT"
  rect 3.68x1.27 smd: 1(-2.475,5.08) 2(2.475,5.08) 3(-2.475,2.54) 4(2.475,2.54) 5(-2.475,0) 6(2.475,0) 7(-2.475,-2.54) 8(2.475,-2.54) 9(-2.475,-5.08) 10(2.475,-5.08)
  silkscreen extent -1.65,-6.35 1.65,6.49, body extent -3.85,-6.35 3.85,6.35, height 9.65
SMC [mil] "Molded Diode, 2-Leads, Body 6.9x5.8mm, IPC Medium Density, based on OnSemi component dimensions and land patterns"
  rect 110x150 smd: 1(-140.49,0) 2(140.49,0)
  silkscreen extent -221,-123 189,124, body extent -156,-116 156,116, height 91
SNT-100-BK-G [mil] "Samtec STEP model"
  round 1 on Mech3: 0(0,0)
  body extent -100,-50 100,50, height 344
SOIC-8 [mm] "duplicate of SO-8.  SOIC, 8-Leads, Body 5.0x4.0mm (max), Pitch 1.27mm, IPC Medium Density"
  rrect17% 1.45x0.6 smd: 1(-2.725,1.905) 2(-2.725,0.635) 3(-2.725,-0.635) 4(-2.725,-1.905) 5(2.725,-1.905) 6(2.725,-0.635) 8(2.725,1.905) C(2.725,0.635)
  silkscreen extent -3.5,-2.5 0.9,2.5, body extent -3,-2.45 3,2.45, height 1.63
SULLINS_PEC04SAAN [mm] "SULLINS"
  rect 1.65x1.65 hole 1: 1(-3.81,0)
  round 1.65 hole 1: 2(-1.27,0) 3(1.27,0) 4(3.81,0)
  silkscreen extent -5.59,-1.4 5.21,1.52, body extent -5.21,-1.33 5.21,1.33, height 8.38
Testpoint_Keystone_Compact [mil] "Compact SMT test point"
  rect 185x135 smd: 1(0,0)
  silkscreen extent -110,-80 110,80, body extent -75,-56 75,56, height 91
TI_Horizontal_Overlay_Small [mil]
  silkscreen extent -545,-68 545,67
WE-LHMI_1040 [mm] "Wurth"
  rect 4.1x3.5 smd: 1(-4.75,0) 2(4.75,0)
  silkscreen extent -5.5,-5.15 5.5,5.15, body extent -5.5,-5.15 5.5,5.15, height 4
WEEE_Minimum [mil] "WEEElie bin"
  silkscreen extent -95,-172 99,104

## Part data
C1 C7: library part CMP-0006669-2, "CAP, CERM, 0.047 uF, 25 V, +/- 10%, X7R, 0402", Cap_Case=0402, Manufacturer=MuRata, Supplier Part Number 1=490-3254-1-ND, TempCo=X7R, Tolerance_%=10%, Value1=Unknown, Value2=25V, ValueDisplayed=0.047uF
C2 C3 C4 C5 C8 C9 C10 C20 C21 C23 C24: library part CMP-0007501-5, "CAP, CERM, 10 uF, 25 V, +/- 20%, X5R, 0603", Cap_Case=0603, Manufacturer=MuRata, Supplier Part Number 1=490-12323-1-ND, TempCo=X5R, Tolerance_%=20%, Value1=Unknown, Value2=25V, ValueDisplayed=10uF
C6 C11 C12 C19 C25: library part CMP-0064946-2, "CAP, CERM, 0.1 uF, 50 V,+/- 10%, X7R, 0402", Cap_Case=0402, Manufacturer=TDK, Supplier Part Number 1=445-173610-1-ND, TempCo=X7R, Tolerance_%=10%, Value1=Unknown, Value2=50V, ValueDisplayed=0.1uF
C13 C14 C15 C16 C17: library part CMP-0007828-2, "CAP, CERM, 10 uF, 25 V, +/- 10%, X5R, 0805", Cap_Case=0805, Manufacturer=TDK, Supplier Part Number 1=445-5984-1-ND, TempCo=X5R, Tolerance_%=10%, Value1=Unknown, Value2=25V, ValueDisplayed=10uF
C18: library part CMP-0007341-5, "CAP, CERM, 4.7 uF, 16 V, +/- 10%, X5R, 0603", Cap_Case=0603, Manufacturer=MuRata, Supplier Part Number 1=490-10481-1-ND, TempCo=X5R, Tolerance_%=10%, Value1=Unknown, Value2=16V, ValueDisplayed=4.7uF
C22: library part CMP-0006235-2, "CAP, CERM, 1000 pF, 50 V, +/- 10%, X7R, 0402", Cap_Case=0402, Manufacturer=Kemet, Supplier Part Number 1=399-1032-1-ND, TempCo=X7R, Tolerance_%=10%, Value1=Unknown, Value2=50V, ValueDisplayed=1000pF
C26: library part CMP-0011556-2, "CAP, TA, 100 uF, 6.3 V, +/- 20%, 0.015 ohm, SMD", Cap_Case=3528-21, Manufacturer=Kemet, Supplier Part Number 1=399-5306-1-ND, Tolerance_%=20%, Value1="0.015 ohm", Value2=6.3V, ValueDisplayed=100uF
C27 C28: library part CMP-0009208-2, "CAP, CERM, 47 uF, 10 V, +/- 10%, X5R, 1210", Cap_Case=1210, Manufacturer=MuRata, Supplier Part Number 1=81-GRM32ER61A476KE20, TempCo=X5R, Tolerance_%=10%, Value1="0.001 ohm", Value2=10V, ValueDisplayed=47uF
C29 C30: library part CMP-0009228-2, "CAP, CERM, 4.7 uF, 50 V, +/- 10%, X7R, 1210", Cap_Case=1210, Manufacturer=MuRata, Supplier Part Number 1=490-1864-1-ND, TempCo=X7R, Tolerance_%=10%, Value1="0.002 ohm", Value2=50V, ValueDisplayed=4.7uF
C31: library part CMP-0008154-2, "CAP, CERM, 0.01 uF, 50 V, +/- 10%, X7R, 0805", Cap_Case=0805, Manufacturer=MuRata, Supplier Part Number 1=490-1664-1-ND, TempCo=X7R, Tolerance_%=10%, Value1=Unknown, Value2=50V, ValueDisplayed=0.01uF
C32: library part CMP-0007443-4, "CAP, CERM, 2200 pF, 50 V, +/- 10%, X7R, 0603", Cap_Case=0603, Manufacturer=MuRata, Supplier Part Number 1=490-1500-1-ND, TempCo=X7R, Tolerance_%=10%, Value1=Unknown, Value2=50V, ValueDisplayed=2200pF
C33: library part CMP-0006727-4, "CAP, CERM, 0.01 uF, 100 V, +/- 10%, X7R, 0603", Cap_Case=0603, Manufacturer=AVX, Supplier Part Number 1=478-1205-1-ND, TempCo=X7R, Tolerance_%=10%, Value1="0.098 ohm", Value2=100V, ValueDisplayed=0.01uF
C34: library part CMP-0007196-4, "CAP, CERM, 22 pF, 50 V, +/- 5%, C0G/NP0, 0603", Cap_Case=0603, Manufacturer=MuRata, Supplier Part Number 1=490-1411-1-ND, TempCo=C0G/NP0, Tolerance_%=5%, Value1=Unknown, Value2=50V, ValueDisplayed=22pF
C35 C36 C37: library part CMP-0006339-4, "CAP, CERM, 10 uF, 10 V, +/- 20%, X5R, 0402", Cap_Case=0402, Manufacturer="Samsung Electro-Mechanics", TempCo=X5R, Tolerance_%=20%, Value1=Unknown, Value2=10V, ValueDisplayed=10uF
C38 C39: library part CMP-0007844-2, "CAP, CERM, 22 uF, 35 V, +/- 20%, X5R, 0805", Cap_Case=0805, Manufacturer=TDK, Supplier Part Number 1=445-14428-1-ND, TempCo=X5R, Tolerance_%=20%, Value1="0.00205 ohm", Value2=35V, ValueDisplayed=22uF
C40 C43: library part CMP-0006370-2, "CAP, CERM, 0.1 uF, 35 V, +/- 10%, X5R, 0402", Cap_Case=0402, Manufacturer="Taiyo Yuden", Supplier Part Number 1=587-1994-1-ND, TempCo=X5R, Tolerance_%=10%, Value1=Unknown, Value2=35V, ValueDisplayed=0.1uF
C41 C42: library part CMP-0009779-2, "CAP, CERM, 330 pF, 50 V, +/- 10%, X7R, 0201", Cap_Case=0201, Manufacturer=MuRata, Supplier Part Number 1=GRM033R71H331KA12D-ND, TempCo=X7R, Tolerance_%=10%, Value1=Unknown, Value2=50V, ValueDisplayed=330pF
C44: library part CMP-0007357-5, "CAP, CERM, 4.7 uF, 35 V, +/- 10%, X5R, 0603", Cap_Case=0603, Manufacturer=MuRata, Supplier Part Number 1=490-7205-1-ND, TempCo=X5R, Tolerance_%=10%, Value1=Unknown, Value2=35V, ValueDisplayed=4.7uF
C45 C46 C47 C48: library part CMP-0006236-2, "CAP, CERM, 0.01 uF, 50 V, +/- 5%, X7R, 0402", Cap_Case=0402, Manufacturer=Kemet, Supplier Part Number 1=399-7758-1-ND, TempCo=X7R, Tolerance_%=5%, Value1=Unknown, Value2=50V, ValueDisplayed=0.01uF
D1: library part CMP-0002827-3, "LED, Green, SMD", Color=green, Manufacturer=Lite-On, Power_TotalModule=100mW, Value1=0.1W, Value2=2.1V
D2: library part CMP-0028510-2, "Diode, Schottky, 40 V, 5 A, SMC", Manufacturer="Comchip Technology", Value1=5A, Value2=0.55V
FID1 FID2 FID3 FID4 FID5 FID6: library part CMP-0077181-1, "Fiducial mark.  There is nothing to buy or mount.", Manufacturer=N/A
H1 H2 H3 H4: library part CMP-0003617-1, "Machine Screw, Round, #4-40 x 1/4, Nylon, Philips panhead", Manufacturer="B&F Fastener Supply", Supplier Part Number 1=H542-ND
H5 H6 H7 H8: library part CMP-0003610-1, "Standoff, Hex, 0.5\"L #4-40 Nylon", Manufacturer=Keystone, Supplier Part Number 1=36-1902C-ND
J1 J2: library part CMP-0074910-1, "Terminal Block, 5.08 mm, 2x1, Brass, TH", Color=Blue, Current_A=15A, Manufacturer="On-Shore Technology", Supplier Part Number 1=ED1609-ND, Voltage_V=300V
J3: library part CMP-0055448-2, "Header (shrouded), 100mil, 5x2, High-Temperature, Gold, TH", Manufacturer=3M, Supplier Part Number 1=MHC10K-ND
J4: library part CMP-0055341-2, "Terminal Block, 3.5 mm, 2x1, Tin, TH", Manufacturer=Molex, Supplier Part Number 1=WM7877-ND
J5: library part CMP-0055598-2, "Header, 2.54mm, 5x2, Gold, SMT", Color=Black, Current_A=5.4A, Manufacturer=Samtec, Supplier Part Number 1=SAM8741-ND, Voltage_V=475V
J6: library part CMP-0085712-2, "Receptacle, USB 3.1 Type C, R/A, Gold, SMT", Color=Black, Current_A=1.25A, Manufacturer="JAE Electronics", Voltage_V=20V
J7: library part CMP-0054562-1, "Header, 100mil, 4x1, Tin, TH", Color=Black, Current_A=3A, Manufacturer="Sullins Connector Solutions", Supplier Part Number 1=S1012E-04-ND, Voltage_V=1.8kV
JP1 JP2 JP3 JP4: library part CMP-0002337-1, "Header, 100mil, 2x1, Tin, TH", Color=Black, Current_A=3A, Manufacturer="Sullins Connector Solutions", PartNumber=PEC02SAAN, Supplier Part Number 1=S1012E-02-ND, Voltage_V=1.8kV
L1: library part CMP-0063290-1, "Inductor, Shielded Drum Core, Powdered Iron, 1 uH, 7 A, 0.0181 ohm, SMD", Manufacturer=Vishay-Dale, Supplier Part Number 1=541-1218-1-ND, Value1="0.0181 ohm", Value2=7A, ValueDisplayed=1uH
L2: library part CMP-0064124-1, "Inductor, Shielded Drum Core, Powdered Iron, 4.7 uH, 7 A, 0.015 ohm, SMD", Manufacturer="Wurth Elektronik", Supplier Part Number 1=732-3389-1-ND, Value1="0.015 ohm", Value2=7A, ValueDisplayed=4.7uH
L3: library part CMP-0003375-1, "Ferrite Bead, 21 ohm @ 100 MHz, 6 A, 0805", Manufacturer="Taiyo Yuden", Supplier Part Number 1=587-1765-1-ND, Value1="0.004 ohm", Value2=6A, ValueDisplayed="21 ohm"
Logo1: library part CMP-0074844-1
Logo2: library part CMP-0074838-1, "Texas Instrument Corporate Signature"
Logo3: library part CMP-0074847-1, "FCC_disclaimer"
Logo4: library part CMP-0074769-1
